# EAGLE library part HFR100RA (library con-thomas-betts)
THOMAS&BETTS
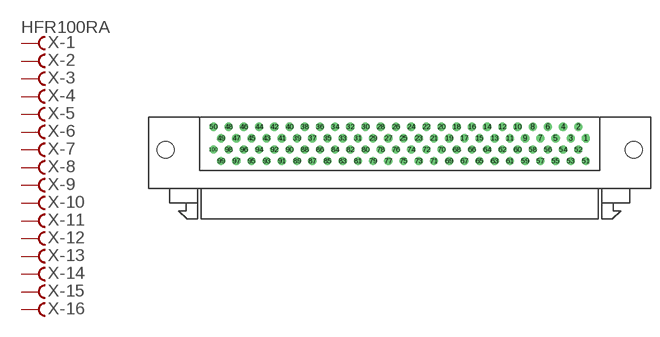
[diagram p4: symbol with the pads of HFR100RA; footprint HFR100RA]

Designator prefix X; gates -1=FV -2=F -3=F -4=F -5=F -6=F -7=F -8=F -9=F -10=F -11=F -12=F -13=F -14=F -15=F -16=F -17=F -18=F -19=F -20=F -21=F -22=F -23=F -24=F -25=F -27=F -28=F -29=F -30=F -31=F -32=F -33=F -34=F -35=F -36=F -37=F -38=F -39=F -40=F -41=F -42=F -43=F -44=F -45=F -46=F -47=F -48=F -49=F -50=F -52=F -53=F -54=F -55=F -56=F -57=F -58=F -59=F -60=F -61=F -62=F -63=F -64=F -65=F -66=F -67=F -68=F -69=F -70=F -71=F -72=F -73=F -74=F -75=F -77=F -78=F -79=F -80=F -81=F -82=F -83=F -84=F -85=F -86=F -87=F -88=F -89=F -90=F -91=F -92=F -93=F -94=F -95=F -96=F -97=F -98=F -99=F -100=F -26=F -51=F -76=F

## HFR100RA (MPN: HFR100RA29CX1; OC_FARNELL: unknown; OC_NEWARK: 92F1766)  [HFR100RA]
1  -1:F  pas
2  -2:F  pas
3  -3:F  pas
4  -4:F  pas
5  -5:F  pas
6  -6:F  pas
7  -7:F  pas
8  -8:F  pas
9  -9:F  pas
10  -10:F  pas
11  -11:F  pas
12  -12:F  pas
13  -13:F  pas
14  -14:F  pas
15  -15:F  pas
16  -16:F  pas
17  -17:F  pas
18  -18:F  pas
19  -19:F  pas
20  -20:F  pas
21  -21:F  pas
22  -22:F  pas
23  -23:F  pas
24  -24:F  pas
25  -25:F  pas
26  -26:F  pas
27  -27:F  pas
28  -28:F  pas
29  -29:F  pas
30  -30:F  pas
31  -31:F  pas
32  -32:F  pas
33  -33:F  pas
34  -34:F  pas
35  -35:F  pas
36  -36:F  pas
37  -37:F  pas
38  -38:F  pas
39  -39:F  pas
40  -40:F  pas
41  -41:F  pas
42  -42:F  pas
43  -43:F  pas
44  -44:F  pas
45  -45:F  pas
46  -46:F  pas
47  -47:F  pas
48  -48:F  pas
49  -49:F  pas
50  -50:F  pas
51  -51:F  pas
52  -52:F  pas
53  -53:F  pas
54  -54:F  pas
55  -55:F  pas
56  -56:F  pas
57  -57:F  pas
58  -58:F  pas
59  -59:F  pas
60  -60:F  pas
61  -61:F  pas
62  -62:F  pas
63  -63:F  pas
64  -64:F  pas
65  -65:F  pas
66  -66:F  pas
67  -67:F  pas
68  -68:F  pas
69  -69:F  pas
70  -70:F  pas
71  -71:F  pas
72  -72:F  pas
73  -73:F  pas
74  -74:F  pas
75  -75:F  pas
76  -76:F  pas
77  -77:F  pas
78  -78:F  pas
79  -79:F  pas
80  -80:F  pas
81  -81:F  pas
82  -82:F  pas
83  -83:F  pas
84  -84:F  pas
85  -85:F  pas
86  -86:F  pas
87  -87:F  pas
88  -88:F  pas
89  -89:F  pas
90  -90:F  pas
91  -91:F  pas
92  -92:F  pas
93  -93:F  pas
94  -94:F  pas
95  -95:F  pas
96  -96:F  pas
97  -97:F  pas
98  -98:F  pas
99  -99:F  pas
100  -100:F  pas

## Footprint HFR100RA (pad centres in mm)
THOMAS&BETTS Fine Pitch "D" Connector HFR100RA29xxx
drill 0.864 octagon: 1 31.115,6.98
drill 0.864 round: 2 29.845,8.89; 3 28.575,6.98; 4 27.305,8.89; 5 26.035,6.98; 6 24.765,8.89; 7 23.495,6.98; 8 22.225,8.89; 9 20.955,6.98; 10 19.685,8.89; 11 18.415,6.98; 12 17.145,8.89; 13 15.875,6.98; 14 14.605,8.89; 15 13.335,6.98; 16 12.065,8.89; 17 10.795,6.98; 18 9.525,8.89; 19 8.255,6.98; 20 6.985,8.89; 21 5.715,6.98; 22 4.445,8.89; 23 3.175,6.98; 24 1.905,8.89; 25 0.635,6.98; 26 -0.635,8.89; 27 -1.905,6.98; 28 -3.175,8.89; 29 -4.445,6.98; 30 -5.715,8.89; 31 -6.985,6.98; 32 -8.255,8.89; 33 -9.525,6.98; 34 -10.795,8.89; 35 -12.065,6.98; 36 -13.335,8.89; 37 -14.605,6.98; 38 -15.875,8.89; 39 -17.145,6.98; 40 -18.415,8.89; 41 -19.685,6.98; 42 -20.955,8.89; 43 -22.225,6.98; 44 -23.495,8.89; 45 -24.765,6.98; 46 -26.035,8.89; 47 -27.305,6.98; 48 -28.575,8.89; 49 -29.845,6.98; 50 -31.115,8.89; 51 31.115,3.16; 52 29.845,5.07; 53 28.575,3.16; 54 27.305,5.07; 55 26.035,3.16; 56 24.765,5.07; 57 23.495,3.16; 58 22.225,5.07; 59 20.955,3.16; 60 19.685,5.07; 61 18.415,3.16; 62 17.145,5.07; 63 15.875,3.16; 64 14.605,5.07; 65 13.335,3.16; 66 12.065,5.07; 67 10.795,3.16; 68 9.525,5.07; 69 8.255,3.16; 70 6.985,5.07; 71 5.715,3.16; 72 4.445,5.07; 73 3.175,3.16; 74 1.905,5.07; 75 0.635,3.16; 76 -0.635,5.07; 77 -1.905,3.16; 78 -3.175,5.07; 79 -4.445,3.16; 80 -5.715,5.07; 81 -6.985,3.16; 82 -8.255,5.07; 83 -9.525,3.16; 84 -10.795,5.07; 85 -12.065,3.16; 86 -13.335,5.07; 87 -14.605,3.16; 88 -15.875,5.07; 89 -17.145,3.16; 90 -18.415,5.07; 91 -19.685,3.16; 92 -20.955,5.07; 93 -22.225,3.16; 94 -23.495,5.07; 95 -24.765,3.16; 96 -26.035,5.07; 97 -27.305,3.16; 98 -28.575,5.07; 99 -29.845,3.16; 100 -31.115,5.07
hole 2.769 at 39.116,5.07
hole 2.769 at -39.116,5.07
